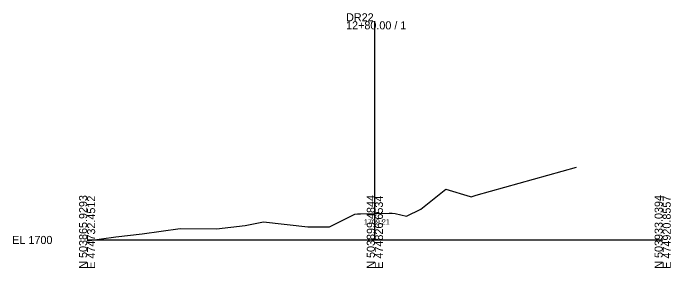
# Model space of a CAD drawing. Extents: x -26 to 1203, y -10 to 9633.
# Drawn here: x -25.7 to 202.8, y 6990.3 to 7078.8 of the extents above; entities that cross this region are included whole.
import ezdxf

# ---------------------------------------------------------------- set-up
doc = ezdxf.new("R2010")
doc.units = 0
for name, color, linetype in [('Exist Cross Section Cell', 7, 'Continuous'), ('Exist XS Center Line Elevation Label', 7, 'Continuous'), ('Exist XS Ground Line', 7, 'Continuous'), ('Scratch_Level_5', 7, 'Continuous')]:
    doc.layers.add(name, color=color, linetype=linetype)

msp = doc.modelspace()

# ---------------------------------------------------------------- linework, layer by layer
at = {"layer": 'Exist Cross Section Cell'}
for p, q in [((100, 7000), (100, 7076)), ((0, 7000), (100, 7000)), ((100, 7000), (200, 7000))]:
    msp.add_line(p, q, dxfattribs=at)
at = {"layer": 'Exist XS Ground Line'}
msp.add_lwpolyline([(0, 6999.69), (9.96, 7001.11), (19.14, 7002.13), (32.36, 7004.02), (44.94, 7003.83), (54.91, 7005.03), (61.28, 7006.27), (76.73, 7004.51), (84.28, 7004.59), (93, 7008.95), (93.98, 7009.03), (95, 7009.11), (100, 7009.21), (105, 7009.31), (106.02, 7009.27), (107, 7009.23), (111, 7008.23), (115.98, 7010.72), (124.68, 7017.61), (133.1, 7015.06), (133.51, 7014.94), (135.24, 7015.57), (170.05, 7025.33)], dxfattribs=at)
at = {"layer": 'Scratch_Level_5'}
msp.add_lwpolyline([(0, 6999.69), (9.96, 7001.11), (19.14, 7002.13), (32.36, 7004.02), (44.94, 7003.83), (54.91, 7005.03), (61.28, 7006.27), (76.73, 7004.51), (84.28, 7004.59), (93, 7008.95), (93.98, 7009.03), (95, 7009.11), (100, 7009.21), (105, 7009.31), (106.02, 7009.27), (107, 7009.23), (111, 7008.23), (115.98, 7010.72), (124.68, 7017.61), (133.1, 7015.06), (133.51, 7014.94), (135.24, 7015.57), (170.05, 7025.33)], dxfattribs=at)

# ---------------------------------------------------------------- texts
at = {"layer": 'Exist Cross Section Cell'}
for s, p in [('DR22', (90, 7076)), ('12+80.00 / 1', (90, 7073.2)), ('EL 1700', (-26, 6998.6))]:
    msp.add_text(s, height=2.8, dxfattribs=at).set_placement(p)
for s, p in [('N 503865.9293', (0, 6990)), ('E 474732.4512', (2.8, 6990)), ('N 503899.4844', (100, 6990)), ('E 474826.6534', (102.8, 6990)), ('N 503933.0394', (200, 6990)), ('E 474920.8557', (202.8, 6990))]:
    msp.add_text(s, height=2.8, rotation=90, dxfattribs=at).set_placement(p)
at = {"layer": 'Exist XS Center Line Elevation Label'}
msp.add_text('1709.21', height=1.8, dxfattribs=at).set_placement((96.2, 7005.41))

doc.saveas('drawing.dxf')
